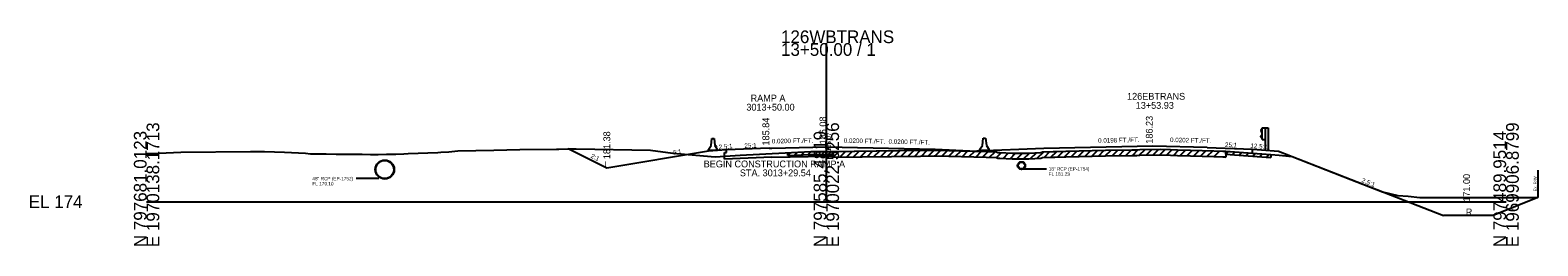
# Model space of a CAD drawing. Extents: x -6494 to 1970605, y -10 to 798140.
# Drawn here: x -25.7 to 307, y 5990.3 to 6037.8 of the extents above; entities that cross this region are included whole.
import ezdxf

# ---------------------------------------------------------------- set-up
doc = ezdxf.new("R2010")
doc.units = 0
for name, color, linetype in [('Default', 7, 'Continuous'), ('RD_GPK_XS_Cell', 7, 'Continuous'), ('RD_XS_Base', 7, 'Continuous'), ('RD_XS_EarthShd', 7, 'Continuous'), ('RD_XS_ExGround', 7, 'Continuous'), ('RD_XS_ExPaveRet', 7, 'Continuous'), ('RD_XS_ExRW', 7, 'Continuous'), ('RD_XS_GR', 7, 'Continuous'), ('RD_XS_Misc_Line', 7, 'Continuous'), ('RD_XS_Pave', 7, 'Continuous'), ('RD_XS_PaveOvlay', 7, 'Continuous'), ('RD_XS_PaveShd', 7, 'Continuous'), ('RD_XS_Pipe', 7, 'Continuous'), ('RD_XS_TieSlope', 7, 'Continuous'), ('RD_XS_TX_Elev_EX', 7, 'Continuous'), ('RD_XS_TX_Elev_PR', 7, 'Continuous'), ('RD_XS_TX_Misc', 7, 'Continuous'), ('RD_XS_TX_MkPT', 7, 'Continuous'), ('RD_XS_TX_Notes', 7, 'Continuous'), ('RD_XS_TX_Profile', 7, 'Continuous'), ('RD_XS_TX_ShdSlope', 7, 'Continuous'), ('RD_XS_TX_Slope', 7, 'Continuous'), ('RD_XS_TX_Station', 7, 'Continuous')]:
    doc.layers.add(name, color=color, linetype=linetype)

msp = doc.modelspace()

# ---------------------------------------------------------------- linework, layer by layer
at = {"layer": 'Default'}
for p, q in [((124, 6011.53), (124.58, 6012.36)), ((124.58, 6012.36), (124.75, 6013.94)), ((124.75, 6013.94), (125.25, 6013.94)), ((125.25, 6013.94), (125.42, 6012.36)), ((125.42, 6012.36), (126, 6011.53)), ((183.89, 6011.56), (184.48, 6012.4)), ((184.48, 6012.4), (184.64, 6013.98)), ((184.64, 6013.98), (185.14, 6013.98)), ((185.14, 6013.98), (185.31, 6012.4)), ((185.31, 6012.4), (185.89, 6011.56)), ((124, 6011.28), (124, 6011.53)), ((126, 6011.28), (124, 6011.28)), ((126, 6011.53), (126, 6011.28)), ((183.89, 6011.31), (183.89, 6011.56)), ((185.89, 6011.31), (183.89, 6011.31)), ((185.89, 6011.56), (185.89, 6011.31))]:
    msp.add_line(p, q, dxfattribs=at)
at = {"layer": 'RD_GPK_XS_Cell'}
for p, q in [((150, 6000), (150, 6034.94)), ((0, 6000), (150, 6000)), ((150, 6000), (300, 6000))]:
    msp.add_line(p, q, dxfattribs=at)
at = {"layer": 'RD_XS_Base'}
for p, q in [((127.5, 6010.86), (128, 6010.88)), ((127.5, 6009.38), (127.5, 6010.86)), ((138, 6009.8), (127.5, 6009.38)), ((128, 6010.88), (128, 6011.44)), ((138, 6009.8), (150, 6010.04)), ((150, 6010.04), (151.5, 6010.01)), ((244.01, 6010.69), (244.01, 6011.59))]:
    msp.add_line(p, q, dxfattribs=at)
at = {"layer": 'RD_XS_EarthShd'}
for p, q in [((128, 6011.44), (124, 6011.12)), ((244.01, 6011.59), (246.01, 6011.43))]:
    msp.add_line(p, q, dxfattribs=at)
at = {"layer": 'RD_XS_ExGround'}
msp.add_line((300, 6000.93), (307.01, 6000.93), dxfattribs=at)
msp.add_lwpolyline([(0, 6010.62), (2.71, 6010.74), (7.58, 6010.93), (22.9, 6011.04), (26.05, 6011.05), (30.42, 6010.93), (35.07, 6010.68), (36.2, 6010.59), (37.08, 6010.57), (39.66, 6010.53), (41.84, 6010.51), (43.8, 6010.5), (45.66, 6010.49), (47.54, 6010.49), (49.41, 6010.41), (51.12, 6010.43), (52.92, 6010.46), (54.97, 6010.52), (56.77, 6010.59), (57.69, 6010.6), (64.25, 6010.85), (64.94, 6010.9), (66.66, 6011.02), (68.66, 6011.19), (76.61, 6011.38), (82.4, 6011.5), (90.44, 6011.6), (91, 6011.61), (92.92, 6011.65), (94.76, 6011.63), (111.2, 6011.38), (116.15, 6010.74), (125.47, 6009.89), (130.99, 6010.28), (146.55, 6011.05), (150, 6011.07), (151.22, 6011.08), (170.8, 6011.33), (173.78, 6011.36), (174.33, 6011.35), (185.3, 6011.1), (187.52, 6010.99), (187.81, 6010.87), (188.3, 6010.84), (190.98, 6010.71), (194.33, 6010.73), (194.71, 6010.73), (197.34, 6010.86), (197.68, 6010.99), (200.05, 6011.07), (200.41, 6011.08), (202.82, 6011.14), (211.57, 6011.35), (217.44, 6011.45), (218.54, 6011.47), (219.16, 6011.48), (223.65, 6011.56), (225.96, 6011.49), (227.49, 6011.44), (230.34, 6011.36), (235.52, 6011.25), (237.46, 6011.15), (237.87, 6011.13), (240.08, 6010.97), (248.12, 6010.39), (249.9, 6010.23), (252.76, 6009.96), (265.77, 6004.91), (272.74, 6002.21), (276.13, 6001.41), (278.4, 6001.22), (280.94, 6000.93), (285.41, 6000.93), (300, 6000.93)], dxfattribs=at)
at = {"layer": 'RD_XS_ExPaveRet'}
for p, q in [((141.49, 6010.17), (141.49, 6010.8)), ((141.49, 6010.17), (146.55, 6010.42)), ((146.55, 6010.42), (150, 6010.44)), ((150, 6010.44), (151.22, 6010.45)), ((151.22, 6010.45), (151.5, 6010.46)), ((151.5, 6009.83), (151.5, 6011.08)), ((151.5, 6011.08), (151.5, 6010.46)), ((151.5, 6009.83), (170.8, 6010.08)), ((170.8, 6010.08), (173.78, 6010.11)), ((173.78, 6010.11), (174.33, 6010.1)), ((174.33, 6010.1), (185.3, 6009.85)), ((185.3, 6009.85), (187.52, 6009.74)), ((187.52, 6009.74), (187.81, 6009.62)), ((187.81, 6009.62), (188.3, 6009.59)), ((188.3, 6009.59), (190.98, 6009.46)), ((190.98, 6009.46), (194.33, 6009.48)), ((194.33, 6009.48), (194.71, 6009.48)), ((194.71, 6009.48), (197.34, 6009.61)), ((197.34, 6009.61), (197.68, 6009.74)), ((197.68, 6009.74), (200.05, 6009.82)), ((200.05, 6009.82), (200.41, 6009.83)), ((200.41, 6009.83), (202.82, 6009.89)), ((202.82, 6009.89), (211.57, 6010.1)), ((211.57, 6010.1), (217.44, 6010.2)), ((217.44, 6010.2), (218.54, 6010.22)), ((218.54, 6010.22), (219.16, 6010.23)), ((219.16, 6010.23), (223.65, 6010.31)), ((223.65, 6010.31), (225.96, 6010.24)), ((225.96, 6010.24), (227.49, 6010.19)), ((227.49, 6010.19), (230.34, 6010.11)), ((230.34, 6010.11), (235.52, 6010)), ((235.52, 6010), (237.46, 6009.9)), ((237.46, 6009.9), (237.87, 6009.88)), ((237.87, 6009.88), (238.12, 6009.86)), ((238.12, 6011.11), (238.12, 6009.86)), ((238.12, 6010.48), (238.12, 6011.11)), ((238.12, 6010.48), (240.08, 6010.35)), ((240.08, 6010.35), (248.12, 6009.77)), ((248.12, 6010.39), (248.12, 6009.77))]:
    msp.add_line(p, q, dxfattribs=at)
at = {"layer": 'RD_XS_ExRW'}
msp.add_line((307.01, 6006.93), (307.01, 6000.93), dxfattribs=at)
at = {"layer": 'RD_XS_GR'}
for p, q in [((246.16, 6016.14), (245.89, 6015.7)), ((245.89, 6015.7), (245.89, 6015.59)), ((245.89, 6015.59), (246.16, 6015.15)), ((246.16, 6016.3), (246.82, 6016.3)), ((246.16, 6013.73), (246.16, 6016.3)), ((246.82, 6016.3), (247.49, 6016.3)), ((246.82, 6016.3), (246.82, 6011.36)), ((247.49, 6016.3), (247.49, 6011.25)), ((245.89, 6014.44), (246.16, 6014.88)), ((245.89, 6014.33), (245.89, 6014.44)), ((246.16, 6013.89), (245.89, 6014.33)), ((246.16, 6013.73), (246.82, 6013.73))]:
    msp.add_line(p, q, dxfattribs=at)
at = {"layer": 'RD_XS_Misc_Line'}
for p, q in [((141.49, 6010.17), (142.15, 6010.83)), ((142.99, 6010.25), (143.65, 6010.9)), ((144.5, 6010.32), (145.15, 6010.98)), ((146, 6010.39), (146.65, 6011.05)), ((147.5, 6010.43), (148.13, 6011.06)), ((149, 6010.44), (149.63, 6011.07)), ((150.5, 6010.45), (151.13, 6011.08)), ((151.5, 6009.83), (152.77, 6011.1)), ((153, 6009.85), (154.27, 6011.12)), ((154.5, 6009.87), (155.77, 6011.14)), ((156.01, 6009.89), (157.27, 6011.16)), ((157.51, 6009.91), (158.77, 6011.17)), ((159.01, 6009.93), (160.28, 6011.19)), ((160.51, 6009.95), (161.78, 6011.21)), ((162.01, 6009.97), (163.28, 6011.23)), ((163.51, 6009.99), (164.78, 6011.25)), ((165.01, 6010.01), (166.28, 6011.27)), ((166.51, 6010.02), (167.78, 6011.29)), ((168.02, 6010.04), (169.28, 6011.31)), ((169.52, 6010.06), (170.78, 6011.33)), ((171.02, 6010.08), (172.28, 6011.35)), ((172.52, 6010.1), (173.78, 6011.36)), ((174.02, 6010.11), (175.24, 6011.33)), ((175.52, 6010.07), (176.75, 6011.3)), ((177.02, 6010.04), (178.25, 6011.26)), ((178.52, 6010.01), (179.75, 6011.23)), ((180.03, 6009.97), (181.25, 6011.19)), ((181.53, 6009.94), (182.75, 6011.16)), ((183.03, 6009.9), (184.25, 6011.12)), ((184.53, 6009.87), (185.74, 6011.08)), ((186.03, 6009.81), (187.22, 6011.01)), ((187.53, 6009.74), (188.62, 6010.83)), ((189.03, 6009.56), (190.23, 6010.75)), ((190.53, 6009.49), (191.77, 6010.72)), ((192.04, 6009.47), (193.29, 6010.72)), ((193.54, 6009.47), (194.8, 6010.73)), ((195.04, 6009.5), (196.35, 6010.81)), ((196.54, 6009.57), (197.97, 6011)), ((198.04, 6009.75), (199.34, 6011.04)), ((199.54, 6009.8), (200.83, 6011.09)), ((201.04, 6009.84), (202.33, 6011.12)), ((202.55, 6009.88), (203.83, 6011.16)), ((204.05, 6009.92), (205.33, 6011.2)), ((205.55, 6009.95), (206.83, 6011.23)), ((207.05, 6009.99), (208.33, 6011.27)), ((208.55, 6010.03), (209.83, 6011.31)), ((210.05, 6010.06), (211.33, 6011.34)), ((211.55, 6010.1), (212.83, 6011.37)), ((213.05, 6010.12), (214.33, 6011.4)), ((214.56, 6010.15), (215.83, 6011.42)), ((216.06, 6010.18), (217.33, 6011.45)), ((217.56, 6010.2), (218.83, 6011.48)), ((219.06, 6010.23), (220.33, 6011.5)), ((220.56, 6010.25), (221.83, 6011.53)), ((222.06, 6010.28), (223.33, 6011.55)), ((223.56, 6010.31), (224.78, 6011.52)), ((225.06, 6010.26), (226.28, 6011.48)), ((226.57, 6010.22), (227.78, 6011.43)), ((228.07, 6010.17), (229.29, 6011.39)), ((229.57, 6010.13), (230.79, 6011.35)), ((231.07, 6010.1), (232.29, 6011.32)), ((232.57, 6010.06), (233.79, 6011.29)), ((234.07, 6010.03), (235.3, 6011.25)), ((235.57, 6010), (236.76, 6011.18)), ((238.12, 6010.48), (238.7, 6011.07)), ((239.62, 6010.38), (240.21, 6010.97)), ((241.12, 6010.27), (241.7, 6010.86)), ((242.62, 6010.17), (243.21, 6010.75)), ((244.12, 6010.06), (244.71, 6010.64)), ((245.63, 6009.95), (246.21, 6010.53)), ((247.13, 6009.84), (247.71, 6010.42))]:
    msp.add_line(p, q, dxfattribs=at)
at = {"layer": 'RD_XS_Pave'}
for p, q in [((138, 6011.84), (150, 6012.08)), ((150, 6012.08), (174, 6011.6)), ((222.01, 6012.23), (198, 6011.76)), ((234.01, 6011.99), (222.01, 6012.23)), ((137.4, 6011.83), (138, 6011.84))]:
    msp.add_line(p, q, dxfattribs=at)
at = {"layer": 'RD_XS_PaveOvlay'}
for p, q in [((151.5, 6011.08), (170.8, 6011.33)), ((151.5, 6011.08), (151.5, 6010.01)), ((170.8, 6011.33), (173.78, 6011.36)), ((173.78, 6011.36), (174.33, 6011.35)), ((174.33, 6011.35), (185.3, 6011.1)), ((185.3, 6011.1), (187.52, 6010.99)), ((187.52, 6010.99), (187.81, 6010.87)), ((187.81, 6010.87), (188.3, 6010.84)), ((188.3, 6010.84), (190.98, 6010.71)), ((190.98, 6010.71), (194.33, 6010.73)), ((194.33, 6010.73), (194.71, 6010.73)), ((194.71, 6010.73), (197.34, 6010.86)), ((197.34, 6010.86), (197.68, 6010.99)), ((197.68, 6010.99), (200.05, 6011.07)), ((200.05, 6011.07), (200.41, 6011.08)), ((200.41, 6011.08), (202.82, 6011.14)), ((202.82, 6011.14), (211.57, 6011.35)), ((211.57, 6011.35), (217.44, 6011.45)), ((217.44, 6011.45), (218.54, 6011.47)), ((218.54, 6011.47), (219.16, 6011.48)), ((219.16, 6011.48), (223.65, 6011.56)), ((223.65, 6011.56), (225.96, 6011.49)), ((225.96, 6011.49), (227.49, 6011.44)), ((227.49, 6011.44), (230.34, 6011.36)), ((230.34, 6011.36), (235.52, 6011.25)), ((235.52, 6011.25), (237.46, 6011.15)), ((237.46, 6011.15), (237.87, 6011.13)), ((237.87, 6011.13), (238.12, 6011.11)), ((238.12, 6011.11), (240.08, 6010.97)), ((240.08, 6010.97), (244.01, 6010.69))]:
    msp.add_line(p, q, dxfattribs=at)
at = {"layer": 'RD_XS_PaveShd'}
for p, q in [((234.01, 6011.99), (244.01, 6011.59)), ((137.4, 6011.83), (128, 6011.44)), ((174, 6011.6), (183.21, 6011.16)), ((198, 6011.76), (183.21, 6011.16))]:
    msp.add_line(p, q, dxfattribs=at)
at = {"layer": 'RD_XS_Pipe'}
for p, q in [((193.56, 6007.23), (198.56, 6007.23)), ((51.22, 6005.1), (46.22, 6005.1))]:
    msp.add_line(p, q, dxfattribs=at)
for centre, radius in [((52.56, 6007.1), 2.1), ((52.56, 6007.1), 2), ((193.06, 6007.98), 0.85), ((193.06, 6007.98), 0.75)]:
    msp.add_circle(centre, radius, dxfattribs=at)
at = {"layer": 'RD_XS_TieSlope'}
for p, q in [((101.56, 6007.38), (93.02, 6011.65)), ((124, 6011.12), (101.56, 6007.38)), ((246.01, 6011.43), (249.76, 6011.13)), ((249.76, 6011.13), (286.2, 5997)), ((307.01, 6000.93), (297.18, 5997))]:
    msp.add_line(p, q, dxfattribs=at)
msp.add_lwpolyline([(297.18, 5997), (286.2, 5997)], dxfattribs=at)

# ---------------------------------------------------------------- texts
at = {"layer": 'RD_GPK_XS_Cell'}
for s, p in [('126WBTRANS', (140, 6034.94)), ('13+50.00 / 1', (140, 6032.14)), ('EL 174', (-26, 5998.6))]:
    msp.add_text(s, height=2.8, dxfattribs=at).set_placement(p)
for s, p in [('N 797681.0123', (0, 5990)), ('E 1970138.1713', (2.8, 5990)), ('N 797585.4819', (150, 5990)), ('E 1970022.5256', (152.8, 5990)), ('N 797489.9514', (300, 5990)), ('E 1969906.8799', (302.8, 5990))]:
    msp.add_text(s, height=2.8, rotation=90, dxfattribs=at).set_placement(p)
at = {"layer": 'RD_XS_ExRW'}
msp.add_text('Ex. R/W ', height=0.65, rotation=90, dxfattribs=at).set_placement((306.76, 6002.31))
at = {"layer": 'RD_XS_Pipe'}
for s, p in [('48" RCP (EP-1752)', (36.58, 6004.72)), ('18" RCP (EP-1754)', (199.06, 6006.86)), ('FL 181.23', (199.06, 6005.73)), ('FL 179.10', (36.58, 6003.6))]:
    msp.add_text(s, height=0.75, dxfattribs=at).set_placement(p)
at = {"layer": 'RD_XS_TX_Elev_EX'}
msp.add_text('185.07', height=1, rotation=90, dxfattribs=at).set_placement((151, 6011.07))
at = {"layer": 'RD_XS_TX_Elev_PR'}
for s, p in [(' 186.08', (150, 6012.08)), (' 186.23', (222.01, 6012.23)), (' 185.84', (137.4, 6011.83))]:
    msp.add_text(s, height=1.5, rotation=90, dxfattribs=at).set_placement(p)
at = {"layer": 'RD_XS_TX_Misc'}
for s, p in [('181.38', (102.31, 6009.38)), ('171.00', (292.03, 6000))]:
    msp.add_text(s, height=1.5, rotation=90, dxfattribs=at).set_placement(p)
at = {"layer": 'RD_XS_TX_MkPT'}
for s, p in [('L', (101.05, 6007.38)), ('R', (291.1, 5997))]:
    msp.add_text(s, height=1.5, dxfattribs=at).set_placement(p)
at = {"layer": 'RD_XS_TX_Notes'}
for s, p in [('BEGIN CONSTRUCTION RAMP A', (122.93, 6007.58)), ('STA. 3013+29.54', (130.92, 6005.62))]:
    msp.add_text(s, height=1.5, dxfattribs=at).set_placement(p)
at = {"layer": 'RD_XS_TX_Profile'}
for rotation, p in [(2.2906, (131.94, 6011.84)), (357.7099, (237.96, 6012.08))]:
    msp.add_text('25:1', height=1, rotation=rotation, dxfattribs=at).set_placement(p)
at = {"layer": 'RD_XS_TX_ShdSlope'}
for rotation, p in [(4.5739, (125.5, 6011.49)), (355.4271, (243.55, 6011.88))]:
    msp.add_text('12.5:1', height=1, rotation=rotation, dxfattribs=at).set_placement(p)
at = {"layer": 'RD_XS_TX_Slope'}
for s, rotation, p in [('0.0200 FT./FT.', 1.1458, (137.98, 6012.84)), ('0.0200 FT./FT.', 358.8542, (153.83, 6013)), ('0.0200 FT./FT.', 358.8542, (163.72, 6012.78)), ('0.0198 FT./FT.', 1.1318, (209.98, 6012.99)), ('0.0202 FT./FT.', 358.8414, (225.83, 6013.15)), ('2:1', 333.4349, (97.9, 6009.77)), ('6:1', 9.4623, (116.22, 6010.33)), ('2.5:1', 338.1986, (268.01, 6004.37))]:
    msp.add_text(s, height=1, rotation=rotation, dxfattribs=at).set_placement(p)
at = {"layer": 'RD_XS_TX_Station'}
for s, p in [('RAMP A', (133.29, 6022.08)), ('126EBTRANS', (216.36, 6022.48)), ('13+53.93', (218.27, 6020.48)), ('3013+50.00', (132.35, 6020.08))]:
    msp.add_text(s, height=1.5, dxfattribs=at).set_placement(p)

doc.saveas('drawing.dxf')
